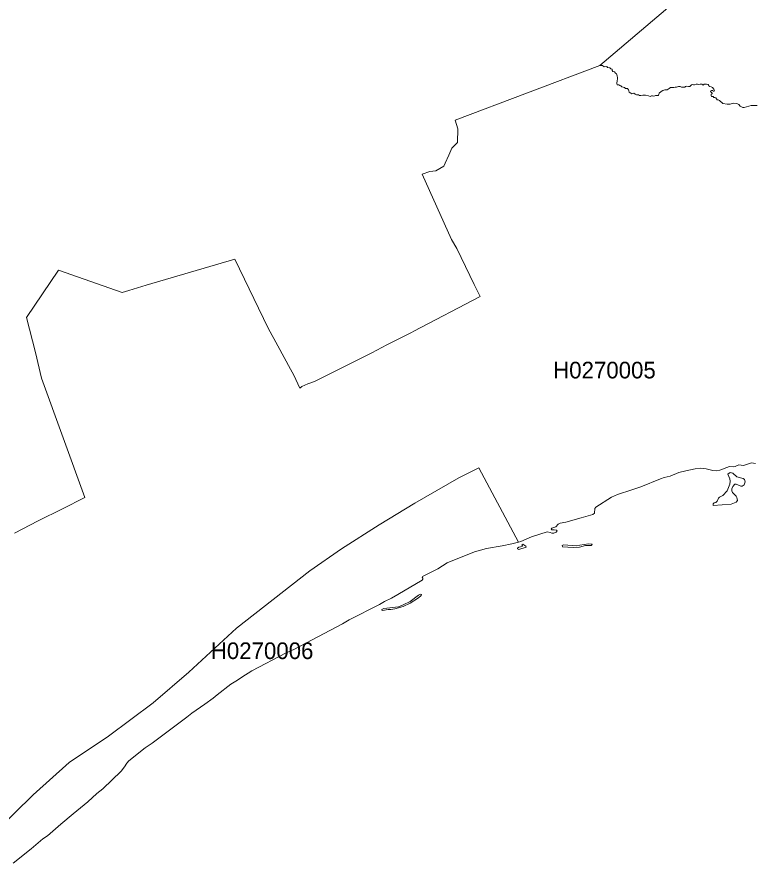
# Model space of a CAD drawing. Extents: x 369010 to 739155, y 6377141 to 6616555.
# Drawn here: x 399245 to 403679, y 6451986 to 6457075 of the extents above; entities that cross this region are included whole.
import ezdxf
from ezdxf.enums import TextEntityAlignment as Align

# ---------------------------------------------------------------- set-up
doc = ezdxf.new("R2010")
doc.units = 0
doc.header["$LTSCALE"] = 40
doc.layers.add('1', color=7, linetype='Continuous', lineweight=13)
doc.layers.add('2', color=7, linetype='Continuous')

msp = doc.modelspace()

# ---------------------------------------------------------------- linework, layer by layer
at = {"layer": '1'}
for points in [[(399230.08, 6453970.76), (399372.58, 6454043.08), (399517.89, 6454117.06), (399652.78, 6454184.92), (399392.77, 6454901.39), (399356.19, 6455057.13), (399302.73, 6455266.65), (399495.71, 6455551.15), (399877.53, 6455417.92), (399918.24, 6455430.17), (400022.84, 6455461.45), (400554.77, 6455617.52), (400756.69, 6455202.44), (400814.28, 6455095.69), (400890.41, 6454955.18), (400910.27, 6454920.58), (400946.52, 6454842.3), (400959.1, 6454851.07), (400995.34, 6454867.95), (401035.23, 6454882.02), (401187.16, 6454958.98), (401378.49, 6455054.15), (401470.51, 6455101.98), (401618.63, 6455176.29), (401631.71, 6455184.23), (402031.73, 6455392.6), (401993.99, 6455464.43), (401890.72, 6455681.57), (401859.27, 6455735.53), (401681.69, 6456128.76), (401728.86, 6456144.65), (401764.28, 6456148.46), (401812.77, 6456176.1), (401820.71, 6456195.79), (401841.73, 6456243.13), (401861.43, 6456285), (401895.52, 6456319.92), (401896.84, 6456400.69), (401881.12, 6456453.15), (402751.01, 6456782.01), (403594.75, 6457499.3)], [(403594.75, 6457499.3), (402751.01, 6456782.01), (402758.13, 6456782.67), (402766.9, 6456783.17), (402777.66, 6456774.23), (402793.38, 6456775.72), (402797.19, 6456770.92), (402810.92, 6456768.93), (402817.38, 6456763.47), (402824.66, 6456760.49), (402825.65, 6456752.22), (402828.63, 6456746.42), (402839.89, 6456743.45), (402844.19, 6456736.49), (402851.14, 6456732.19), (402854.28, 6456720.28), (402857.26, 6456708.52), (402858.09, 6456700.58), (402855.77, 6456691.31), (402852.8, 6456673.77), (402854.28, 6456665.33), (402865.04, 6456666.32), (402871.83, 6456661.85), (402877.29, 6456661.02), (402884.08, 6456654.57), (402898.81, 6456650.1), (402905.59, 6456644.31), (402917.34, 6456643.81), (402923.3, 6456636.86), (402925.78, 6456630.57), (402927.27, 6456621.3), (402936.54, 6456616.84), (402943.82, 6456612.04), (402948.79, 6456613.36), (402954.58, 6456615.84), (402962.52, 6456611.04), (402970.8, 6456606.08), (402983.54, 6456606.08), (402989.83, 6456602.6), (402997.28, 6456601.61), (403008.53, 6456605.08), (403026.08, 6456604.59), (403044.12, 6456600.12), (403054.54, 6456595.32), (403061.33, 6456599.29), (403068.12, 6456600.12), (403076.56, 6456597.31), (403081.03, 6456599.62), (403086.49, 6456601.61), (403101.55, 6456601.61), (403104.03, 6456604.09), (403105.52, 6456608.06), (403108, 6456615.84), (403119.26, 6456625.61), (403129.02, 6456631.56), (403142.26, 6456635.37), (403155.5, 6456635.37), (403162.29, 6456639.34), (403168.74, 6456643.81), (403176.52, 6456650.6), (403195.55, 6456649.6), (403203.5, 6456652.58), (403212.27, 6456652.58), (403217.23, 6456654.57), (403224.02, 6456656.06), (403233.79, 6456656.06), (403242.06, 6456652.58), (403261.26, 6456652.58), (403266.06, 6456656.56), (403270.53, 6456657.55), (403283.27, 6456656.06), (403291.22, 6456656.56), (403299.66, 6456664), (403305.45, 6456667.81), (403314.22, 6456666.49), (403320.67, 6456665.99), (403330.44, 6456669.3), (403338.22, 6456669.8), (403347.16, 6456668.31), (403353.44, 6456670.29), (403364.7, 6456669.8), (403370.66, 6456665.99), (403372.97, 6456665), (403377.94, 6456669.8), (403392.67, 6456669.8), (403401.94, 6456667.81), (403406.74, 6456663.01), (403409.22, 6456655.23), (403421.47, 6456654.74), (403428.91, 6456649.77)], [(403283.27, 6456656.06), (403270.53, 6456657.55), (403266.06, 6456656.56), (403261.26, 6456652.58), (403242.06, 6456652.58), (403233.79, 6456656.06), (403224.02, 6456656.06), (403217.23, 6456654.57), (403212.27, 6456652.58), (403203.5, 6456652.58), (403195.55, 6456649.6), (403176.52, 6456650.6), (403168.74, 6456643.81), (403162.29, 6456639.34), (403155.5, 6456635.37), (403142.26, 6456635.37), (403129.02, 6456631.56), (403119.26, 6456625.61), (403108, 6456615.84), (403105.52, 6456608.06), (403104.03, 6456604.09), (403101.55, 6456601.61), (403086.49, 6456601.61), (403081.03, 6456599.62), (403076.56, 6456597.31), (403068.12, 6456600.12), (403061.33, 6456599.29), (403054.54, 6456595.32), (403044.12, 6456600.12), (403026.08, 6456604.59), (403008.53, 6456605.08), (402997.28, 6456601.61), (402989.83, 6456602.6), (402983.54, 6456606.08), (402970.8, 6456606.08), (402962.52, 6456611.04), (402954.58, 6456615.84), (402948.79, 6456613.36), (402943.82, 6456612.04), (402936.54, 6456616.84), (402927.27, 6456621.3), (402925.78, 6456630.57), (402923.3, 6456636.86), (402917.34, 6456643.81), (402905.59, 6456644.31), (402898.81, 6456650.1), (402884.08, 6456654.57), (402877.29, 6456661.02), (402871.83, 6456661.85), (402865.04, 6456666.32), (402854.28, 6456665.33), (402852.8, 6456673.77), (402855.77, 6456691.31), (402858.09, 6456700.58), (402857.26, 6456708.52), (402854.28, 6456720.28), (402851.14, 6456732.19), (402844.19, 6456736.49), (402839.89, 6456743.45), (402828.63, 6456746.42), (402825.65, 6456752.22), (402824.66, 6456760.49), (402817.38, 6456763.47), (402810.92, 6456768.93), (402797.19, 6456770.92), (402793.38, 6456775.72), (402777.66, 6456774.23), (402766.9, 6456783.17), (402758.13, 6456782.67), (402751.01, 6456782.01), (401881.12, 6456453.15), (401896.84, 6456400.69), (401895.52, 6456319.92), (401861.43, 6456285), (401841.73, 6456243.13), (401820.71, 6456195.79), (401812.77, 6456176.1), (401764.28, 6456148.46), (401728.86, 6456144.65), (401681.69, 6456128.76), (401859.27, 6455735.53), (401890.72, 6455681.57), (401993.99, 6455464.43), (402031.73, 6455392.6), (401631.71, 6455184.23), (401618.63, 6455176.29), (401470.51, 6455101.98), (401378.49, 6455054.15), (401187.16, 6454958.98), (401035.23, 6454882.02), (400995.34, 6454867.95), (400959.1, 6454851.07), (400946.52, 6454842.3), (400910.27, 6454920.58), (400890.41, 6454955.18), (400814.28, 6455095.69), (400756.69, 6455202.44), (400554.77, 6455617.52), (400022.84, 6455461.45), (399918.24, 6455430.17)], [(403697.86, 6456542.03), (403661.94, 6456542.03), (403619.24, 6456529.61), (403611.13, 6456530.77), (403595.08, 6456537.56), (403586.97, 6456546.99), (403574.89, 6456554.61), (403552.71, 6456555.1), (403534.51, 6456549.14), (403517.46, 6456550.96), (403490.98, 6456553.78), (403471.45, 6456571.32), (403461.68, 6456575.29), (403455.73, 6456576.78), (403447.95, 6456587.54), (403442.49, 6456591.02), (403436.69, 6456591.02), (403433.22, 6456596.31), (403422.96, 6456596.81), (403419.48, 6456602.77), (403419.48, 6456609.55), (403426.43, 6456612.04), (403426.43, 6456616.01), (403417.16, 6456625.77), (403418.49, 6456630.57), (403421.96, 6456632.56), (403428.91, 6456632.06), (403433.71, 6456628.25), (403437.69, 6456628.75), (403439.67, 6456633.05), (403436.69, 6456639.51), (403428.91, 6456649.77), (403421.47, 6456654.74), (403409.22, 6456655.23), (403406.74, 6456663.01), (403401.94, 6456667.81), (403392.67, 6456669.8), (403377.94, 6456669.8), (403372.97, 6456665), (403370.66, 6456665.99), (403364.7, 6456669.8), (403353.44, 6456670.29), (403347.16, 6456668.31), (403338.22, 6456669.8), (403330.44, 6456669.3), (403320.67, 6456665.99), (403314.22, 6456666.49), (403305.45, 6456667.81), (403299.66, 6456664), (403291.22, 6456656.56), (403283.27, 6456656.06)], [(403428.91, 6456649.77), (403436.69, 6456639.51), (403439.67, 6456633.05), (403437.69, 6456628.75), (403433.71, 6456628.25), (403428.91, 6456632.06), (403421.96, 6456632.56), (403418.49, 6456630.57), (403417.16, 6456625.77), (403426.43, 6456616.01), (403426.43, 6456612.04), (403419.48, 6456609.55), (403419.48, 6456602.77), (403422.96, 6456596.81), (403433.22, 6456596.31), (403436.69, 6456591.02), (403442.49, 6456591.02), (403447.95, 6456587.54), (403455.73, 6456576.78), (403461.68, 6456575.29), (403471.45, 6456571.32), (403490.98, 6456553.78), (403517.46, 6456550.96), (403534.51, 6456549.14), (403552.71, 6456555.1), (403574.89, 6456554.61), (403586.97, 6456546.99), (403595.08, 6456537.56), (403611.13, 6456530.77), (403619.24, 6456529.61), (403661.94, 6456542.03), (403697.86, 6456542.03)], [(399918.24, 6455430.17), (399877.53, 6455417.92), (399495.71, 6455551.15), (399302.73, 6455266.65), (399356.19, 6455057.13), (399392.77, 6454901.39), (399652.78, 6454184.92), (399517.89, 6454117.06), (399372.58, 6454043.08), (399230.08, 6453970.76)], [(399119.02, 6452179.67), (399342.29, 6452395.82), (399558.11, 6452591.45), (399796.1, 6452749.34), (400063.23, 6452948.44), (400279.04, 6453133.8), (400564.54, 6453397.95), (401005.77, 6453742.36), (401196.1, 6453876.25), (401423.01, 6454020.41), (401638.82, 6454150.83), (401902.31, 6454301.77), (402023.12, 6454363.66), (402260.95, 6453916.14), (402274.86, 6453919.95), (402340.06, 6453946.76), (402434.4, 6453977.54), (402452.28, 6453973.57), (402461.21, 6453969.93), (402475.11, 6453970.59), (402488.02, 6453976.22), (402493.65, 6453983.5), (402490.34, 6453988.8), (402477.1, 6453990.12), (402462.54, 6453989.46), (402458.9, 6453995.42), (402462.54, 6453999.72), (402486.04, 6454007.33), (402500.27, 6454024.88), (402513.18, 6454030.84), (402546.12, 6454035.14), (402638.14, 6454062.94), (402709.14, 6454081.48), (402718.57, 6454090.09), (402721.22, 6454117.23), (402726.18, 6454125.34), (402821.35, 6454187.24), (402856.27, 6454202.46), (402943.82, 6454231.26), (402998.27, 6454247.81), (403114.79, 6454297.46), (403138.29, 6454304.58), (403174.2, 6454313.18), (403226.5, 6454333.71), (403268.04, 6454344.96), (403324.32, 6454357.54), (403355.1, 6454360.19), (403373.97, 6454359.2), (403390.19, 6454355.89), (403429.74, 6454345.95), (403449.6, 6454344.3), (403472.11, 6454348.93), (403531.69, 6454369.79), (403554.86, 6454368.13), (403564.13, 6454369.79), (403587.3, 6454379.88), (403614.44, 6454376.57), (403663.93, 6454393.45), (403686.44, 6454388.16)], [(399221.64, 6451985.54), (399330.7, 6452071.43), (399400.88, 6452131.35), (399429.34, 6452150.21), (399508.95, 6452220.39), (399582.77, 6452282.12), (399671.31, 6452353.29), (399725.6, 6452404.26), (399761.01, 6452431.4), (399871.74, 6452539.15), (399892.59, 6452564.3), (399906.49, 6452586.15), (399918.74, 6452600.05), (400015.89, 6452679.33), (400058.92, 6452705.81), (400083.09, 6452725.67), (400267.62, 6452864.03), (400296.75, 6452887.37), (400375.03, 6452940.66), (400424.69, 6452976.74), (400449.18, 6452996.6), (400530.44, 6453060.82), (400571.82, 6453084.65), (400597.64, 6453103.02), (400656.89, 6453141.09), (400863.44, 6453249.33), (400910.11, 6453270.51), (401203.22, 6453424.59), (401243.77, 6453449.42), (401425.82, 6453540.61), (401454.78, 6453557.82), (401497.81, 6453578.02), (401535.05, 6453600.52), (401681.69, 6453687.91), (401686.98, 6453693.04), (401686.98, 6453699.99), (401682.02, 6453704.96), (401685, 6453709.92), (401776.52, 6453755.27), (401832.79, 6453790.69), (401997.8, 6453857.55), (402069.13, 6453877.08), (402163.8, 6453893.3), (402221.23, 6453904.72), (402260.95, 6453916.14), (402023.12, 6454363.66), (401902.31, 6454301.77), (401638.82, 6454150.83), (401423.01, 6454020.41), (401196.1, 6453876.25), (401005.77, 6453742.36), (400564.54, 6453397.95), (400279.04, 6453133.8), (400063.23, 6452948.44), (399796.1, 6452749.34), (399558.11, 6452591.45), (399342.29, 6452395.82), (399119.02, 6452179.67)]]:
    msp.add_lwpolyline(points, dxfattribs=at)
for points in [[(403534.51, 6454334.54), (403520.77, 6454325.6), (403533.68, 6454297.3), (403535, 6454282.07), (403533.68, 6454265.19), (403517.29, 6454223.81), (403490.98, 6454195.35), (403470.79, 6454187.07), (403463.84, 6454181.11), (403457.22, 6454161.58), (403448.28, 6454153.97), (403438.02, 6454152.98), (403432.39, 6454145.69), (403431.73, 6454137.09), (403539.97, 6454143.71), (403571.08, 6454155.29), (403578.03, 6454166.55), (403575.72, 6454184.09), (403570.42, 6454193.03), (403548.9, 6454213.88), (403543.94, 6454224.81), (403543.94, 6454236.72), (403550.56, 6454251.29), (403562.31, 6454263.53), (403571.58, 6454264.53), (403598.39, 6454251.95), (403607, 6454252.28), (403619.24, 6454259.89), (403624.21, 6454278.43), (403620.24, 6454293.32), (403613.95, 6454299.28), (403574.56, 6454307.89), (403550.73, 6454331.22)], [(402286.77, 6453904.39), (402280.81, 6453899.76), (402286.44, 6453892.64), (402282.8, 6453888.67), (402263.6, 6453885.36), (402255.33, 6453880.39), (402255.66, 6453875.76), (402263.93, 6453872.45), (402307.29, 6453886.02), (402305.64, 6453891.48)], [(402681.66, 6453905.05), (402631.19, 6453898.1), (402612.98, 6453892.97), (402531.39, 6453900.25), (402525.1, 6453895.62), (402526.59, 6453887.01), (402590.31, 6453883.7), (402629.03, 6453885.19), (402665.11, 6453894.79), (402698.55, 6453896.45), (402704.83, 6453900.75), (402702.85, 6453904.39)], [(401678.05, 6453601.52), (401671.43, 6453602.18), (401660.84, 6453596.88), (401609.53, 6453559.15), (401566.99, 6453537.96), (401540.18, 6453527.04), (401452.63, 6453515.79), (401439.72, 6453510.82), (401439.06, 6453507.51), (401443.69, 6453504.53), (401478.45, 6453511.48), (401493.68, 6453510.49), (401516.85, 6453514.79), (401568.48, 6453529.36), (401609.53, 6453548.89), (401659.51, 6453581.66), (401676.39, 6453595.56)]]:
    msp.add_lwpolyline(points, close=True, dxfattribs=at)

# ---------------------------------------------------------------- texts
at = {"layer": '2'}
for s, p in [('H0270005', (402778.71, 6454900.56)), ('H0270006', (400719.51, 6453212.67))]:
    msp.add_text(s, height=100, dxfattribs=at).set_placement(p, align=Align.CENTER)

doc.saveas('drawing.dxf')
